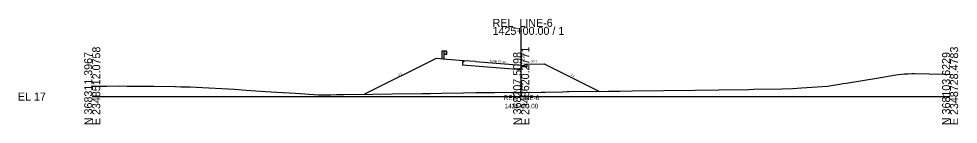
# Model space of a CAD drawing. Extents: x -26 to 403, y -10 to 6565.
# Drawn here: x -25.7 to 302.8, y 4990.3 to 5027.3 of the extents above; entities that cross this region are included whole.
import ezdxf

# ---------------------------------------------------------------- set-up
doc = ezdxf.new("R2010")
doc.units = 0
for name, color, linetype in [('RD_GPK_XS_Cell', 7, 'Continuous'), ('RD_XS_Base', 7, 'Continuous'), ('RD_XS_CurbBase', 7, 'Continuous'), ('RD_XS_CurbFront', 7, 'Continuous'), ('RD_XS_CurbTop', 7, 'Continuous'), ('RD_XS_EarthShd', 7, 'Continuous'), ('RD_XS_ExGround', 7, 'Continuous'), ('RD_XS_GR', 7, 'Continuous'), ('RD_XS_Pave', 7, 'Continuous'), ('RD_XS_PaveShd', 7, 'Continuous'), ('RD_XS_TieSlope', 7, 'Continuous'), ('RD_XS_TX_Elev_EX', 7, 'Continuous'), ('RD_XS_TX_Elev_PR', 7, 'Continuous'), ('RD_XS_TX_Slope', 7, 'Continuous'), ('RD_XS_TX_Station', 7, 'Continuous'), ('RD_XS_TX_TOC', 7, 'Continuous')]:
    doc.layers.add(name, color=color, linetype=linetype)

msp = doc.modelspace()

# ---------------------------------------------------------------- linework, layer by layer
at = {"layer": 'RD_GPK_XS_Cell'}
for p, q in [((150, 5000), (150, 5024.42)), ((0, 5000), (150, 5000)), ((150, 5000), (300, 5000))]:
    msp.add_line(p, q, dxfattribs=at)
at = {"layer": 'RD_XS_Base'}
for p, q in [((129.99, 5012.11), (129.49, 5012.15)), ((129.49, 5012.15), (129.49, 5010.96)), ((149.99, 5009.32), (129.49, 5010.96)), ((129.99, 5012.56), (129.99, 5012.11))]:
    msp.add_line(p, q, dxfattribs=at)
at = {"layer": 'RD_XS_CurbBase'}
for p, q in [((151.49, 5010.36), (149.99, 5010.44)), ((149.99, 5009.32), (149.99, 5010.44)), ((151.99, 5010.36), (151.49, 5010.36)), ((151.99, 5011.36), (151.99, 5010.36))]:
    msp.add_line(p, q, dxfattribs=at)
at = {"layer": 'RD_XS_CurbFront'}
msp.add_line((149.99, 5010.44), (149.99, 5010.94), dxfattribs=at)
at = {"layer": 'RD_XS_CurbTop'}
for p, q in [((149.99, 5010.96), (149.99, 5010.94)), ((149.99, 5010.94), (151.41, 5010.86)), ((151.41, 5010.86), (151.49, 5011.36)), ((151.49, 5011.36), (151.99, 5011.36))]:
    msp.add_line(p, q, dxfattribs=at)
at = {"layer": 'RD_XS_EarthShd'}
for p, q in [((120.24, 5013.34), (95.17, 5000.8)), ((123.99, 5013.04), (120.24, 5013.34)), ((129.99, 5012.56), (123.99, 5013.04)), ((151.99, 5011.36), (157.99, 5011.48))]:
    msp.add_line(p, q, dxfattribs=at)
at = {"layer": 'RD_XS_ExGround'}
msp.add_lwpolyline([(0, 5003.59), (3.52, 5003.64), (5.04, 5003.67), (9.7, 5003.71), (12.23, 5003.67), (13.63, 5003.65), (21.53, 5003.61), (28.96, 5003.5), (31.01, 5003.45), (34.28, 5003.43), (40.74, 5003.08), (45.3, 5002.79), (49.74, 5002.56), (53.86, 5002.24), (60.57, 5001.82), (64.57, 5001.5), (71.1, 5001.14), (79.16, 5000.64), (83.49, 5000.62), (85.41, 5000.67), (87.98, 5000.72), (98.15, 5000.86), (104.93, 5000.98), (115.23, 5001.08), (116.67, 5001.1), (118.27, 5001.09), (122.11, 5001.14), (129.85, 5001.3), (134.19, 5001.38), (140.69, 5001.46), (142.4, 5001.49), (146.53, 5001.47), (150, 5001.42), (150.78, 5001.41), (157.02, 5001.49), (158.34, 5001.53), (164.44, 5001.71), (166.09, 5001.74), (166.65, 5001.78), (180.54, 5001.9), (184.45, 5001.95), (188.81, 5002), (199.86, 5002.13), (210.82, 5002.21), (219.05, 5002.38), (229.79, 5002.5), (231.22, 5002.54), (241.16, 5002.71), (244.99, 5002.81), (248.05, 5003.03), (257.18, 5003.62), (262, 5004.46), (262.53, 5004.56), (263.71, 5004.74), (274.37, 5006.47), (281.08, 5007.58), (283.99, 5008.02), (285.35, 5008), (286.66, 5008.09), (287.45, 5008.14), (298.16, 5007.79), (299.98, 5007.72), (300, 5007.72)], dxfattribs=at)
at = {"layer": 'RD_XS_GR'}
for p, q in [((122.91, 5015.87), (122.24, 5015.87)), ((122.24, 5015.87), (122.24, 5013.18)), ((123.83, 5015.87), (122.91, 5015.87)), ((122.91, 5015.87), (122.91, 5013.13)), ((123.83, 5014.7), (122.91, 5014.7)), ((123.83, 5014.7), (123.83, 5015.87)), ((123.83, 5015.8), (123.99, 5015.6)), ((123.99, 5015.55), (123.83, 5015.35)), ((123.99, 5015.03), (123.83, 5015.23)), ((123.83, 5014.78), (123.99, 5014.98)), ((123.99, 5015.6), (123.99, 5015.55)), ((123.99, 5014.98), (123.99, 5015.03))]:
    msp.add_line(p, q, dxfattribs=at)
at = {"layer": 'RD_XS_Pave'}
msp.add_line((133.99, 5012.24), (149.99, 5010.96), dxfattribs=at)
at = {"layer": 'RD_XS_PaveShd'}
msp.add_line((133.99, 5012.24), (129.99, 5012.56), dxfattribs=at)
at = {"layer": 'RD_XS_TieSlope'}
msp.add_line((157.99, 5011.48), (177.21, 5001.87), dxfattribs=at)

# ---------------------------------------------------------------- texts
at = {"layer": 'RD_GPK_XS_Cell'}
for s, p in [('REL_LINE-6', (140, 5024.42)), ('1425+00.00 / 1', (140, 5021.62)), ('EL 17', (-26, 4998.6))]:
    msp.add_text(s, height=2.8, dxfattribs=at).set_placement(p)
for s, p in [('E 2348512.0758', (2.8, 4990)), ('E 2348620.2771', (152.8, 4990)), ('E 2348728.4783', (302.8, 4990)), ('N 368311.3967', (0, 4990)), ('N 368207.5098', (150, 4990)), ('N 368103.6229', (300, 4990))]:
    msp.add_text(s, height=2.8, rotation=90, dxfattribs=at).set_placement(p)
at = {"layer": 'RD_XS_TX_Elev_EX'}
msp.add_text('18.42', height=1, rotation=90, dxfattribs=at).set_placement((150.5, 5001.42))
at = {"layer": 'RD_XS_TX_Elev_PR'}
msp.add_text('27.96', height=1.2, rotation=90, dxfattribs=at).set_placement((151.2, 5010.96))
at = {"layer": 'RD_XS_TX_Slope'}
for s, rotation, p in [('0.080 FT./FT.', 355.4261, (138.99, 5012.09)), ('50:1', 1.1458, (153.6, 5011.93)), ('2:1', 26.5651, (107.12, 5007.19)), ('2:1', 333.4349, (167.27, 5007.42))]:
    msp.add_text(s, height=0.75, rotation=rotation, dxfattribs=at).set_placement(p)
at = {"layer": 'RD_XS_TX_Station'}
for s, p in [('REL_LINE-6', (143.92, 4998.79)), ('1425+00.00', (144.23, 4995.89))]:
    msp.add_text(s, height=1.6, dxfattribs=at).set_placement(p)
at = {"layer": 'RD_XS_TX_TOC'}
msp.add_text('TOCRT', height=0.05, dxfattribs=at).set_placement((151.21, 5011.31))

doc.saveas('drawing.dxf')
